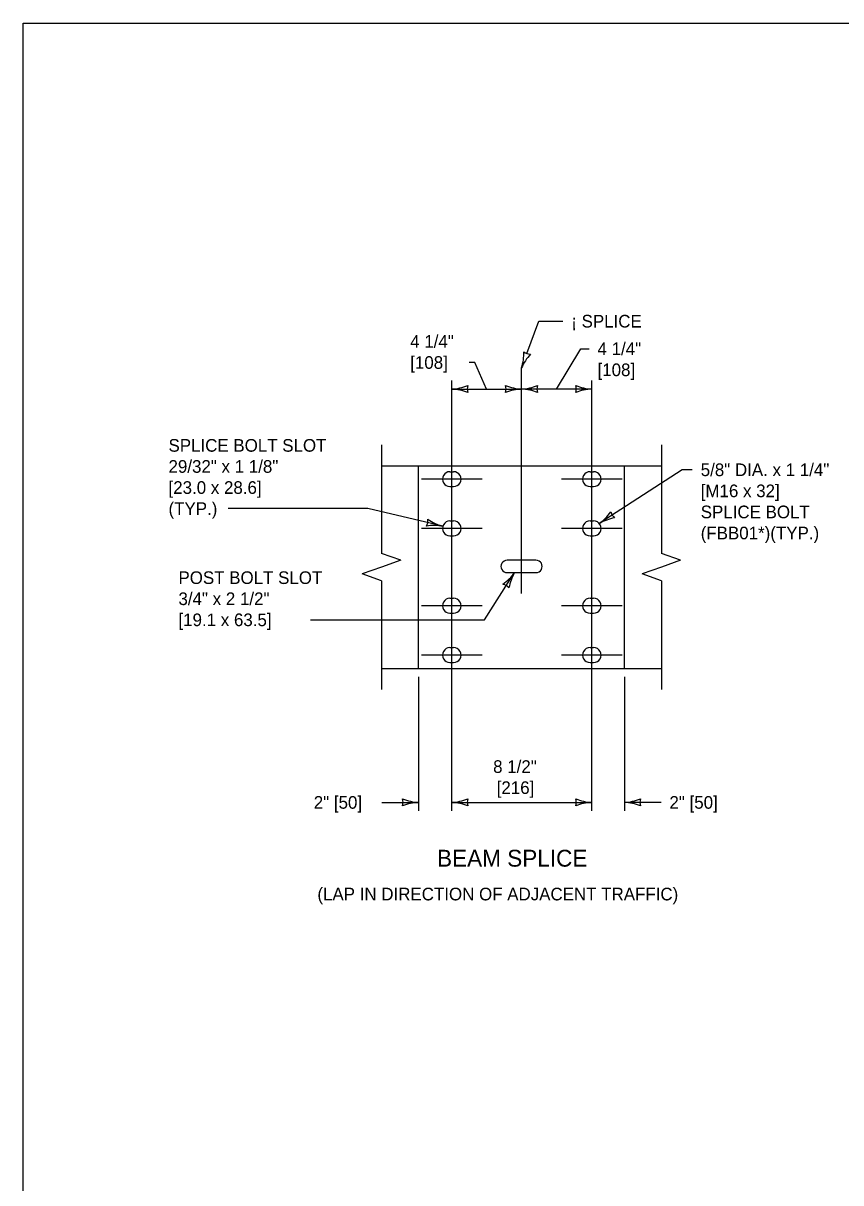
# Model space of a CAD drawing. Extents: x 49991.4 to 50021, y 49987.6 to 50011.4.
# Drawn here: x 49999.38 to 50003.26, y 49993.5 to 49999 of the extents above; entities that cross this region are included whole.
import ezdxf

# ---------------------------------------------------------------- set-up
doc = ezdxf.new("R2010")
doc.units = 0
for name, color, linetype in [('Level 1', 7, 'Continuous'), ('Level 2', 7, 'Continuous'), ('Level 3', 7, 'Continuous'), ('Level 4', 7, 'Continuous'), ('Level 5', 7, 'Continuous'), ('Level 6', 7, 'Continuous')]:
    doc.layers.add(name, color=color, linetype=linetype)

msp = doc.modelspace()

# ---------------------------------------------------------------- linework, layer by layer
at = {"layer": 'Level 1'}
for p, q in [((50001.0835, 49996.8994), (50002.4105, 49996.8994)), ((50001.2586, 49995.938), (50001.2586, 49996.8994)), ((50001.4077, 49996.8715), (50001.4248, 49996.8715)), ((50002.0721, 49996.8715), (50002.0892, 49996.8715)), ((50001.4077, 49996.8007), (50001.4248, 49996.8007)), ((50002.0721, 49996.8007), (50002.0892, 49996.8007)), ((50001.4077, 49996.6376), (50001.4248, 49996.6376)), ((50002.0721, 49996.6376), (50002.0892, 49996.6376)), ((50001.4077, 49996.5668), (50001.4248, 49996.5668)), ((50002.0721, 49996.5668), (50002.0892, 49996.5668)), ((50001.8156, 49996.4514), (50001.6789, 49996.4514)), ((50001.6789, 49996.3928), (50001.8156, 49996.3928)), ((50001.4077, 49996.2707), (50001.4248, 49996.2707)), ((50002.0721, 49996.2707), (50002.0892, 49996.2707)), ((50001.4077, 49996.1999), (50001.4248, 49996.1999)), ((50002.0721, 49996.1999), (50002.0892, 49996.1999)), ((50001.4077, 49996.0367), (50001.4248, 49996.0367)), ((50002.0721, 49996.0367), (50002.0892, 49996.0367)), ((50001.0835, 49995.938), (50002.4105, 49995.938)), ((50001.4077, 49995.9659), (50001.4248, 49995.9659)), ((50002.0721, 49995.9659), (50002.0892, 49995.9659))]:
    msp.add_line(p, q, dxfattribs=at)
msp.add_lwpolyline([(49999.3835, 49998.9992), (50016.7501, 49998.9992), (50016.7501, 49987.7988), (49999.3835, 49987.7988)], close=True, dxfattribs=at)
for centre, major_axis, ratio, start_param, end_param in [((50001.4077, 49996.8361), (-0.0354, 0), 0.998676, 4.712389, 7.853982), ((50001.4248, 49996.8361), (-0.0354, 0), 0.998676, 1.570796, 4.712389), ((50002.0721, 49996.8361), (-0.0354, 0), 0.998676, 4.712389, 7.853982), ((50002.0892, 49996.8361), (-0.0354, 0), 0.998676, 1.570796, 4.712389), ((50001.4077, 49996.6022), (-0.0354, 0), 0.998676, 4.712389, 7.853982), ((50001.4248, 49996.6022), (-0.0354, 0), 0.998676, 1.570796, 4.712389), ((50002.0721, 49996.6022), (-0.0354, 0), 0.998676, 4.712389, 7.853982), ((50002.0892, 49996.6022), (-0.0354, 0), 0.998676, 1.570796, 4.712389), ((50001.6789, 49996.4221), (-0.0294, 0), 0.995211, 4.712389, 7.853982), ((50001.8156, 49996.4221), (-0.0296, 0), 0.988923, 1.570796, 4.712389), ((50001.4077, 49996.2353), (-0.0354, 0), 0.998676, 4.712389, 7.853982), ((50001.4248, 49996.2353), (-0.0354, 0), 0.998676, 1.570796, 4.712389), ((50002.0721, 49996.2353), (-0.0354, 0), 0.998676, 4.712389, 7.853982), ((50002.0892, 49996.2353), (-0.0354, 0), 0.998676, 1.570796, 4.712389), ((50001.4077, 49996.0013), (-0.0354, 0), 0.998676, 4.712389, 7.853982), ((50001.4248, 49996.0013), (-0.0354, 0), 0.998676, 1.570796, 4.712389), ((50002.0721, 49996.0013), (-0.0354, 0), 0.998676, 4.712389, 7.853982), ((50002.0892, 49996.0013), (-0.0354, 0), 0.998676, 1.570796, 4.712389)]:
    msp.add_ellipse(centre, major_axis=major_axis, ratio=ratio, start_param=start_param, end_param=end_param, dxfattribs=at)
at = {"layer": 'Level 3'}
for p, q in [((50001.7729, 49997.4322), (50001.8301, 49997.5854)), ((50001.8301, 49997.5854), (50001.9432, 49997.5854)), ((50001.4162, 49997.2634), (50001.7472, 49997.2634)), ((50002.0806, 49997.2634), (50001.7472, 49997.2634)), ((50002.5094, 49996.8805), (50002.1161, 49996.6251)), ((50002.5573, 49996.8805), (50002.5094, 49996.8805)), ((50001.0182, 49996.6962), (50000.3564, 49996.6962)), ((50001.3737, 49996.6123), (50001.0182, 49996.6962)), ((50001.571, 49996.1686), (50001.7146, 49996.3928)), ((50000.7461, 49996.1686), (50001.571, 49996.1686)), ((50001.2586, 49995.898), (50001.2586, 49995.2624)), ((50002.2354, 49995.898), (50002.2354, 49995.2624)), ((50001.0852, 49995.3024), (50001.2586, 49995.3024)), ((50001.4162, 49995.3024), (50002.0806, 49995.3024)), ((50002.4089, 49995.3024), (50002.2354, 49995.3024))]:
    msp.add_line(p, q, dxfattribs=at)
for points in [[(50001.9139, 49997.2634), (50002.0281, 49997.4547), (50002.0678, 49997.4547)], [(50001.5817, 49997.2634), (50001.5256, 49997.3894), (50001.4996, 49997.3894)]]:
    msp.add_lwpolyline(points, dxfattribs=at)
for centre, radius, start, end in [((50001.5252, 49997.4341), 0.233, 342.3483, 1.5982), ((50001.9521, 49997.2771), 0.2223, 136.977, 157.1606), ((50001.7921, 49997.4835), 0.0548, 231.6599, 267.3822), ((50001.4047, 49997.4962), 0.233, 272.8273, 292.0772), ((50001.4071, 49997.0413), 0.2223, 67.456, 87.6395), ((50001.5444, 49997.2634), 0.0548, 162.1388, 197.8612), ((50001.7564, 49997.4856), 0.2223, 247.456, 267.6395), ((50001.619, 49997.2634), 0.0548, 342.1388, 17.8612), ((50001.7587, 49997.0307), 0.233, 92.8273, 112.0772), ((50001.7357, 49997.4962), 0.233, 272.8273, 292.0772), ((50001.7381, 49997.0413), 0.2223, 67.456, 87.6395), ((50001.8754, 49997.2634), 0.0548, 162.1388, 197.8612), ((50002.0898, 49997.4856), 0.2223, 247.456, 267.6395), ((50001.9524, 49997.2634), 0.0548, 342.1388, 17.8612), ((50002.0921, 49997.0307), 0.233, 92.8273, 112.0772), ((50001.2489, 49996.6417), 0.0548, 328.8502, 4.5725), ((50001.4337, 49996.8264), 0.2223, 234.1674, 254.3509), ((50001.9794, 49996.8138), 0.233, 305.9216, 325.1715), ((50002.2297, 49996.434), 0.2223, 100.5503, 120.7338), ((50002.2235, 49996.6951), 0.0548, 195.2331, 230.9555), ((50001.3314, 49996.3832), 0.233, 79.5387, 98.7885), ((50001.5324, 49996.5203), 0.2223, 304.8248, 325.0083), ((50001.9167, 49996.277), 0.233, 150.1961, 169.446), ((50001.6454, 49996.2848), 0.0548, 39.5076, 75.23), ((50001.2678, 49995.5246), 0.2223, 247.456, 267.6395), ((50001.1304, 49995.3024), 0.0548, 342.1388, 17.8612), ((50001.4047, 49995.5352), 0.233, 272.8273, 292.0772), ((50001.5444, 49995.3024), 0.0548, 162.1388, 197.8612), ((50002.0898, 49995.5246), 0.2223, 247.456, 267.6395), ((50001.9524, 49995.3024), 0.0548, 342.1388, 17.8612), ((50002.2239, 49995.5352), 0.233, 272.8273, 292.0772), ((50002.3636, 49995.3024), 0.0548, 162.1388, 197.8612), ((50001.2701, 49995.0697), 0.233, 92.8273, 112.0772), ((50001.4071, 49995.0803), 0.2223, 67.456, 87.6395), ((50002.0921, 49995.0697), 0.233, 92.8273, 112.0772), ((50002.2263, 49995.0803), 0.2223, 67.456, 87.6395)]:
    msp.add_arc(centre, radius, start, end, dxfattribs=at)
at = {"layer": 'Level 4'}
msp.add_line((50002.2354, 49995.938), (50002.2354, 49996.8994), dxfattribs=at)
at = {"layer": 'Level 5'}
for p, q in [((50001.7472, 49996.2928), (50001.7472, 49997.3634)), ((50001.4162, 49995.2624), (50001.4162, 49997.3034)), ((50002.0806, 49995.2624), (50002.0806, 49997.3034)), ((50001.5602, 49996.8361), (50001.2723, 49996.8361)), ((50002.2246, 49996.8361), (50001.9367, 49996.8361)), ((50001.5602, 49996.6022), (50001.2723, 49996.6022)), ((50002.2246, 49996.6022), (50001.9367, 49996.6022)), ((50001.5602, 49996.2353), (50001.2723, 49996.2353)), ((50002.2246, 49996.2353), (50001.9367, 49996.2353)), ((50001.5602, 49996.0013), (50001.2723, 49996.0013)), ((50002.2246, 49996.0013), (50001.9367, 49996.0013))]:
    msp.add_line(p, q, dxfattribs=at)
at = {"layer": 'Level 6'}
for p, q in [((50001.0835, 49996.9994), (50001.0835, 49996.4836)), ((50002.4105, 49996.9994), (50002.4105, 49996.4836)), ((50001.1749, 49996.4512), (50001.0835, 49996.4836)), ((50002.5019, 49996.4512), (50002.4105, 49996.4836)), ((50001.0835, 49996.4188), (50000.9921, 49996.3864)), ((50001.1749, 49996.4512), (50001.0835, 49996.4188)), ((50002.4105, 49996.4188), (50002.3191, 49996.3864)), ((50002.5019, 49996.4512), (50002.4105, 49996.4188)), ((50001.0835, 49996.354), (50000.9921, 49996.3864)), ((50002.4105, 49996.354), (50002.3191, 49996.3864)), ((50001.0835, 49996.354), (50001.0835, 49995.838)), ((50002.4105, 49996.354), (50002.4105, 49995.838))]:
    msp.add_line(p, q, dxfattribs=at)

# ---------------------------------------------------------------- texts
at = {"layer": 'Level 2'}
for s, height, p in [('¡ SPLICE', 0.06, (50001.9832, 49997.5554)), ('4 1/4"', 0.06, (50001.2192, 49997.4594)), ('4 1/4"', 0.06, (50002.1078, 49997.4247)), ('[108]', 0.06, (50001.2192, 49997.3594)), ('[108]', 0.06, (50002.1078, 49997.3247)), ('SPLICE BOLT SLOT', 0.06, (50000.0728, 49996.9662)), ('29/32" x 1 1/8"', 0.06, (50000.0728, 49996.8662)), ('5/8" DIA. x 1 1/4"', 0.06, (50002.5973, 49996.8505)), ('[23.0 x 28.6]', 0.06, (50000.0728, 49996.7662)), ('[M16 x 32]', 0.06, (50002.5973, 49996.7505)), ('(TYP.)', 0.06, (50000.0728, 49996.6662)), ('SPLICE BOLT ', 0.06, (50002.5973, 49996.6505)), ('(FBB01*)(TYP.) ', 0.06, (50002.5973, 49996.5505)), ('POST BOLT SLOT', 0.06, (50000.12, 49996.3386)), ('3/4" x 2 1/2"', 0.06, (50000.12, 49996.2386)), ('[19.1 x 63.5]', 0.06, (50000.12, 49996.1386)), ('8 1/2"', 0.06, (50001.6126, 49995.4424)), ('[216]', 0.06, (50001.6294, 49995.3424)), ('2" [50]', 0.06, (50000.7617, 49995.2724)), ('2" [50]', 0.06, (50002.4489, 49995.2724)), ('BEAM SPLICE', 0.08, (50001.3464, 49994.9976)), ('(LAP IN DIRECTION OF ADJACENT TRAFFIC)', 0.06, (50000.779, 49994.8376))]:
    msp.add_text(s, height=height, dxfattribs=at).set_placement(p)

doc.saveas('drawing.dxf')
